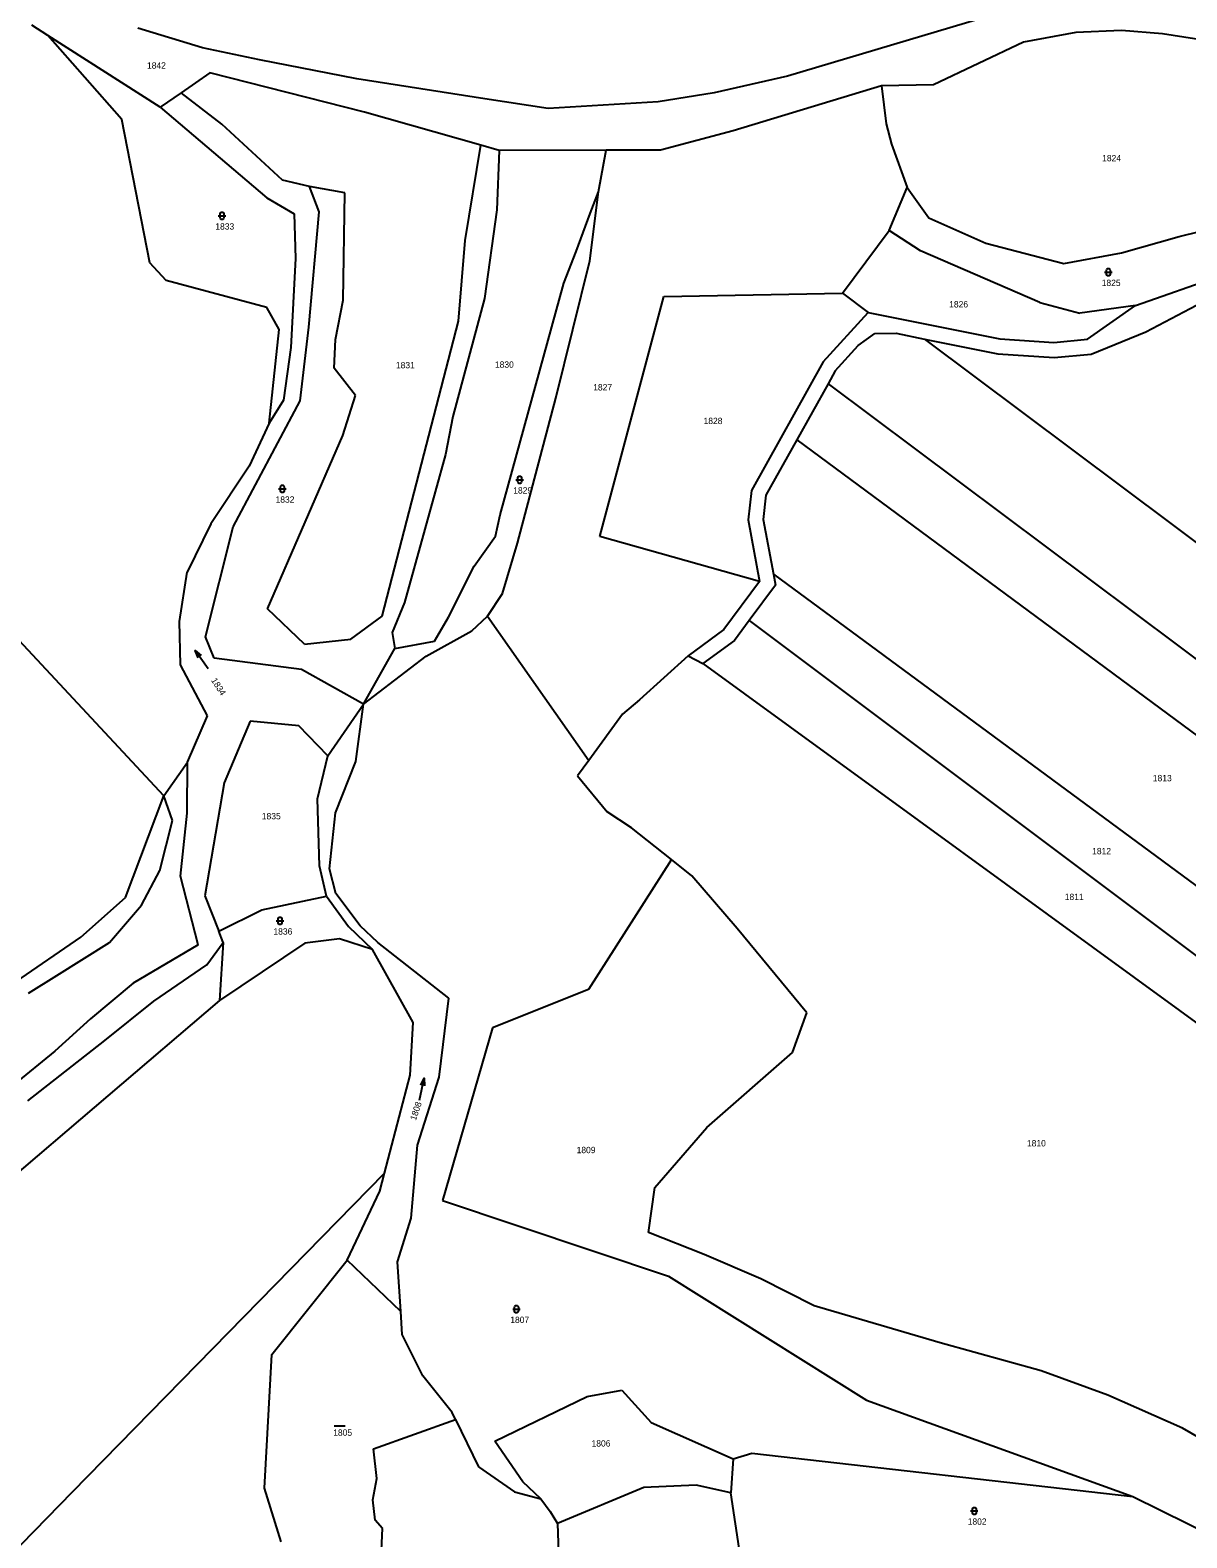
# Model space of a CAD drawing. Extents: x -802857 to -799647, y -1020285 to -1015884.
# Drawn here: x -802140.5 to -801830.8, y -1017652.7 to -1017248.9 of the extents above; entities that cross this region are included whole.
import ezdxf

# ---------------------------------------------------------------- set-up
doc = ezdxf.new("R2010")
doc.units = 0
for name, color, linetype in [('Default', 7, 'Continuous'), ('KN_HRANICE', 7, 'Continuous'), ('KN_KULTURY', 7, 'Continuous'), ('KN_PARCELY', 7, 'Continuous')]:
    doc.layers.add(name, color=color, linetype=linetype)

# ---------------------------------------------------------------- blocks, each defined once
blk = doc.blocks.new('316')
at = {"layer": 'Default'}
for points in [[(-1, 1), (0.27, 1), (1, 1)], [(-0.5, 1.5), (-0.4, 1.79), (-0.15, 1.97), (0.16, 1.97), (0.41, 1.79), (0.51, 1.5), (0.51, 0.5), (0.41, 0.21), (0.16, 0.03), (-0.15, 0.03), (-0.4, 0.21), (-0.5, 0.5), (-0.5, 1.5)]]:
    blk.add_lwpolyline(points, dxfattribs=at)
blk = doc.blocks.new('802')
at = {"layer": 'Default'}
blk.add_line((-3, 0), (3, 0), dxfattribs=at)
blk.add_lwpolyline([(1, 0.5), (3, 0), (1, -0.5)], dxfattribs=at)
blk = doc.blocks.new('804')
at = {"layer": 'Default'}
blk.add_line((-1.5, 0), (1.5, 0), dxfattribs=at)

msp = doc.modelspace()

# ---------------------------------------------------------------- linework, layer by layer
at = {"layer": 'KN_HRANICE'}
for p, q in [((-802135.82, -1017250.34), (-802140.07, -1017247.63)), ((-802094.38, -1017253.69), (-802111.69, -1017248.4)), ((-801885.86, -1017245.79), (-801937.77, -1017261.22)), ((-802115.97, -1017272.85), (-802135.82, -1017250.34)), ((-802105.66, -1017269.56), (-802135.82, -1017250.34)), ((-801874.58, -1017252.18), (-801898.61, -1017263.57)), ((-801860.52, -1017249.56), (-801874.58, -1017252.18)), ((-801848.33, -1017249.03), (-801860.52, -1017249.56)), ((-801837.36, -1017249.87), (-801848.33, -1017249.03)), ((-801825.91, -1017251.69), (-801837.36, -1017249.87)), ((-802079.15, -1017256.83), (-802094.38, -1017253.69)), ((-802092.36, -1017260.39), (-802100.06, -1017265.7)), ((-802050.96, -1017270.85), (-802092.36, -1017260.39)), ((-802053.05, -1017261.93), (-802079.15, -1017256.83)), ((-802018.77, -1017267.32), (-802053.05, -1017261.93)), ((-801937.77, -1017261.22), (-801957.35, -1017265.73)), ((-801912.59, -1017263.88), (-801952.27, -1017275.87)), ((-801898.61, -1017263.57), (-801912.59, -1017263.88)), ((-801912.59, -1017263.88), (-801911.34, -1017274.02)), ((-802100.06, -1017265.7), (-802105.66, -1017269.56)), ((-802089.22, -1017274.06), (-802100.06, -1017265.7)), ((-802001.86, -1017269.94), (-802018.77, -1017267.32)), ((-801972.34, -1017268.15), (-802001.86, -1017269.94)), ((-801957.35, -1017265.73), (-801972.34, -1017268.15)), ((-802105.66, -1017269.56), (-802077.17, -1017293.84)), ((-802019.81, -1017279.73), (-802050.96, -1017270.85)), ((-802108.43, -1017311.28), (-802115.97, -1017272.85)), ((-802072.93, -1017289.09), (-802089.22, -1017274.06)), ((-801952.27, -1017275.87), (-801971.78, -1017281.07)), ((-801911.34, -1017274.02), (-801909.91, -1017279.49)), ((-802024.05, -1017305.27), (-802019.81, -1017279.73)), ((-802014.98, -1017281.11), (-802019.81, -1017279.73)), ((-801909.91, -1017279.49), (-801905.73, -1017291.03)), ((-802014.98, -1017281.11), (-802015.53, -1017297.03)), ((-801986.28, -1017281.08), (-802014.98, -1017281.11)), ((-801988.37, -1017292.2), (-801986.28, -1017281.08)), ((-801971.78, -1017281.07), (-801986.28, -1017281.08)), ((-802065.76, -1017290.83), (-802072.93, -1017289.09)), ((-802063.17, -1017297.59), (-802065.76, -1017290.83)), ((-802056.25, -1017292.52), (-802065.76, -1017290.83)), ((-802056.66, -1017321.24), (-802056.25, -1017292.52)), ((-801990.7, -1017310.73), (-801988.37, -1017292.2)), ((-801990.6, -1017297.99), (-801988.37, -1017292.2)), ((-801910.52, -1017302.62), (-801905.73, -1017291.03)), ((-801905.73, -1017291.03), (-801899.92, -1017299.2)), ((-802077.17, -1017293.84), (-802069.8, -1017298.14)), ((-802015.53, -1017297.03), (-802018.85, -1017320.82)), ((-802069.8, -1017298.14), (-802069.48, -1017310.1)), ((-802065.91, -1017328.48), (-802063.17, -1017297.59)), ((-801994.28, -1017308.23), (-801990.6, -1017297.99)), ((-801899.92, -1017299.2), (-801884.62, -1017305.93)), ((-801832.86, -1017304.19), (-801816.89, -1017300.2)), ((-801922.99, -1017319.4), (-801910.52, -1017302.62)), ((-801902.09, -1017308), (-801910.52, -1017302.62)), ((-801848.32, -1017308.55), (-801832.86, -1017304.19)), ((-802025.84, -1017326.85), (-802024.05, -1017305.27)), ((-801997.65, -1017316.67), (-801994.28, -1017308.23)), ((-801870.21, -1017321.88), (-801902.09, -1017308)), ((-801884.62, -1017305.93), (-801863.71, -1017311.42)), ((-801863.71, -1017311.42), (-801848.32, -1017308.55)), ((-802104.1, -1017315.93), (-802108.43, -1017311.28)), ((-802069.48, -1017310.1), (-802070.75, -1017333.91)), ((-801999.74, -1017347.44), (-801990.7, -1017310.73)), ((-802104.72, -1017453.99), (-802234.28, -1017315.12)), ((-802077.12, -1017323.21), (-802104.1, -1017315.93)), ((-802014.71, -1017378.73), (-801997.65, -1017316.67)), ((-801844.56, -1017322.69), (-801821.66, -1017314.59)), ((-802058.72, -1017331.81), (-802056.66, -1017321.24)), ((-802018.85, -1017320.82), (-802027.34, -1017352.4)), ((-801987.95, -1017384.56), (-801970.88, -1017320.22)), ((-801970.88, -1017320.22), (-801922.99, -1017319.4)), ((-801922.99, -1017319.4), (-801916.15, -1017324.52)), ((-801841.82, -1017329.72), (-801824.8, -1017320.76)), ((-802073.83, -1017329.13), (-802077.12, -1017323.21)), ((-801928.21, -1017337.78), (-801916.15, -1017324.52)), ((-801916.15, -1017324.52), (-801880.89, -1017331.62)), ((-801870.21, -1017321.88), (-801859.44, -1017324.75)), ((-801844.56, -1017322.69), (-801859.44, -1017324.75)), ((-801857.38, -1017331.72), (-801844.56, -1017322.69)), ((-802076.48, -1017354.13), (-802073.83, -1017329.13)), ((-802068.2, -1017348.18), (-802065.91, -1017328.48)), ((-802046.3, -1017405.83), (-802025.84, -1017326.85)), ((-802059.12, -1017339.45), (-802058.72, -1017331.81)), ((-801924.94, -1017340.13), (-801918.78, -1017333.36)), ((-801918.78, -1017333.36), (-801914.38, -1017330.18)), ((-801914.38, -1017330.18), (-801908.67, -1017330.11)), ((-801908.67, -1017330.11), (-801901.1, -1017331.64)), ((-801901.1, -1017331.64), (-801881.43, -1017335.59)), ((-801901.1, -1017331.64), (-801752.52, -1017442.84)), ((-801880.89, -1017331.62), (-801866.4, -1017332.56)), ((-801866.4, -1017332.56), (-801857.38, -1017331.72)), ((-801856.42, -1017335.65), (-801841.82, -1017329.72)), ((-802070.75, -1017333.91), (-802072.65, -1017348.05)), ((-801881.43, -1017335.59), (-801866.34, -1017336.57)), ((-801866.34, -1017336.57), (-801856.42, -1017335.65)), ((-802053.38, -1017346.72), (-802059.12, -1017339.45)), ((-801928.21, -1017337.78), (-801947.39, -1017372.21)), ((-801924.94, -1017340.13), (-801926.87, -1017343.6)), ((-801926.87, -1017343.6), (-801935.26, -1017358.65)), ((-801926.87, -1017343.6), (-801768.75, -1017461.94)), ((-802086.2, -1017381.95), (-802068.2, -1017348.18)), ((-802072.65, -1017348.05), (-802076.48, -1017354.13)), ((-802056.78, -1017357.44), (-802053.38, -1017346.72)), ((-802010.06, -1017386.33), (-801999.74, -1017347.44)), ((-802027.34, -1017352.4), (-802029.33, -1017362.55)), ((-802076.48, -1017354.13), (-802081.89, -1017365.72)), ((-802076.93, -1017403.91), (-802056.78, -1017357.44)), ((-801935.26, -1017358.65), (-801943.51, -1017373.46)), ((-801935.26, -1017358.65), (-801779.08, -1017474.09)), ((-802029.33, -1017362.55), (-802034.83, -1017382.57)), ((-802081.89, -1017365.72), (-802092.18, -1017381.13)), ((-801947.39, -1017372.21), (-801948.3, -1017380.1)), ((-801943.51, -1017373.46), (-801944.26, -1017379.96)), ((-802092.18, -1017381.13), (-802098.46, -1017394.03)), ((-802015.89, -1017384.46), (-802014.71, -1017378.73)), ((-801948.3, -1017380.1), (-801945.23, -1017396.56)), ((-801944.26, -1017379.96), (-801941.53, -1017394.58)), ((-802093.54, -1017411.38), (-802086.2, -1017381.95)), ((-802034.83, -1017382.57), (-802040.31, -1017402.18)), ((-802021.65, -1017392.45), (-802015.89, -1017384.46)), ((-801945.23, -1017396.56), (-801987.95, -1017384.56)), ((-802014.08, -1017399.77), (-802010.06, -1017386.33)), ((-802028.5, -1017406.11), (-802021.65, -1017392.45)), ((-802100.54, -1017407.26), (-802098.46, -1017394.03)), ((-801945.23, -1017396.56), (-801954.81, -1017409.47)), ((-801940.98, -1017397.54), (-801947.99, -1017406.99)), ((-801941.53, -1017394.58), (-801940.98, -1017397.54)), ((-801941.53, -1017394.58), (-801799.52, -1017499.3)), ((-802018.05, -1017405.89), (-802014.08, -1017399.77)), ((-802067.06, -1017413.33), (-802076.93, -1017403.91)), ((-802054.67, -1017411.98), (-802046.3, -1017405.83)), ((-802040.31, -1017402.18), (-802043.62, -1017410.23)), ((-802022.25, -1017409.81), (-802018.05, -1017405.89)), ((-802018.05, -1017405.89), (-801990.91, -1017444.47)), ((-802100.23, -1017418.86), (-802100.54, -1017407.26)), ((-802034.52, -1017416.58), (-802022.25, -1017409.81)), ((-802032.22, -1017412.54), (-802028.5, -1017406.11)), ((-801954.81, -1017409.47), (-801964.29, -1017416.44)), ((-801947.99, -1017406.99), (-801951.96, -1017412.34)), ((-801947.99, -1017406.99), (-801809.18, -1017511.2)), ((-802091.22, -1017417.12), (-802093.54, -1017411.38)), ((-802067.06, -1017413.33), (-802054.67, -1017411.98)), ((-802043.62, -1017410.23), (-802042.85, -1017414.5)), ((-802042.85, -1017414.5), (-802032.22, -1017412.54)), ((-801951.96, -1017412.34), (-801960.43, -1017418.57)), ((-802067.89, -1017420.13), (-802091.22, -1017417.12)), ((-802051.27, -1017429.42), (-802042.85, -1017414.5)), ((-802051.27, -1017429.42), (-802034.52, -1017416.58)), ((-801964.29, -1017416.44), (-801977.33, -1017428.3)), ((-801964.29, -1017416.44), (-801960.43, -1017418.57)), ((-802093.06, -1017432.53), (-802100.23, -1017418.86)), ((-802051.27, -1017429.42), (-802067.89, -1017420.13)), ((-801960.43, -1017418.57), (-801819.24, -1017521.36)), ((-802060.85, -1017443.3), (-802051.27, -1017429.42)), ((-802053.3, -1017444.75), (-802051.27, -1017429.42)), ((-801977.33, -1017428.3), (-801981.94, -1017432.13)), ((-802098.34, -1017444.92), (-802093.06, -1017432.53)), ((-802081.64, -1017433.99), (-802088.57, -1017450.52)), ((-802068.53, -1017435.23), (-802081.64, -1017433.99)), ((-801981.94, -1017432.13), (-801990.91, -1017444.47)), ((-802060.85, -1017443.3), (-802068.53, -1017435.23)), ((-802104.72, -1017453.99), (-802098.34, -1017444.92)), ((-802098.44, -1017458.57), (-802098.34, -1017444.92)), ((-802063.57, -1017454.79), (-802060.85, -1017443.3)), ((-802058.8, -1017458.48), (-802053.3, -1017444.75)), ((-801990.91, -1017444.47), (-801993.92, -1017448.6)), ((-801993.92, -1017448.6), (-801986, -1017458.26)), ((-802115.01, -1017481.22), (-802104.72, -1017453.99)), ((-802102.44, -1017460.62), (-802104.72, -1017453.99)), ((-802088.57, -1017450.52), (-802093.7, -1017480.76)), ((-802063.08, -1017472.7), (-802063.57, -1017454.79)), ((-802060.32, -1017473.5), (-802058.8, -1017458.48)), ((-801979.48, -1017462.54), (-801986, -1017458.26)), ((-802105.82, -1017473.99), (-802102.44, -1017460.62)), ((-802100.3, -1017475.48), (-802098.44, -1017458.57)), ((-801968.81, -1017471.06), (-801979.48, -1017462.54)), ((-802110.74, -1017483.29), (-802105.82, -1017473.99)), ((-802061.2, -1017480.82), (-802063.08, -1017472.7)), ((-802058.68, -1017480.13), (-802060.32, -1017473.5)), ((-801968.81, -1017471.06), (-801991.01, -1017505.82)), ((-801963.34, -1017475.43), (-801968.81, -1017471.06)), ((-802095.56, -1017493.88), (-802100.3, -1017475.48)), ((-801951.18, -1017489.47), (-801963.34, -1017475.43)), ((-802126.91, -1017491.79), (-802115.01, -1017481.22)), ((-802093.7, -1017480.76), (-802089.98, -1017490.25)), ((-802078.47, -1017484.51), (-802061.2, -1017480.82)), ((-802061.2, -1017480.82), (-802055.25, -1017488.94)), ((-802052.12, -1017488.76), (-802058.68, -1017480.13)), ((-802119.31, -1017493.23), (-802110.74, -1017483.29)), ((-802089.98, -1017490.25), (-802078.47, -1017484.51)), ((-802088.79, -1017493.29), (-802089.98, -1017490.25)), ((-802055.25, -1017488.94), (-802048.87, -1017495.15)), ((-802047.43, -1017493.24), (-802052.12, -1017488.76)), ((-801932.6, -1017512.07), (-801951.18, -1017489.47)), ((-802144.39, -1017503.8), (-802126.91, -1017491.79)), ((-802133.41, -1017502.05), (-802119.31, -1017493.23)), ((-802095.56, -1017493.88), (-802112.95, -1017504.15)), ((-802093.25, -1017499.27), (-802088.79, -1017493.29)), ((-802088.79, -1017493.29), (-802089.8, -1017508.76)), ((-802066.93, -1017493.44), (-802089.8, -1017508.76)), ((-802057.71, -1017492.3), (-802066.93, -1017493.44)), ((-802048.87, -1017495.15), (-802057.71, -1017492.3)), ((-802028.39, -1017508.13), (-802047.43, -1017493.24)), ((-802037.98, -1017514.66), (-802048.87, -1017495.15)), ((-802140.95, -1017506.78), (-802133.41, -1017502.05)), ((-802107.41, -1017508.95), (-802093.25, -1017499.27)), ((-802112.95, -1017504.15), (-802124.38, -1017513.72)), ((-801991.01, -1017505.82), (-802016.71, -1017516.13)), ((-802089.8, -1017508.76), (-802158.4, -1017567.31)), ((-802120.51, -1017519.45), (-802107.41, -1017508.95)), ((-802031.03, -1017529.3), (-802028.39, -1017508.13)), ((-802124.38, -1017513.72), (-802133.87, -1017522.32)), ((-802038.74, -1017528.77), (-802037.98, -1017514.66)), ((-801936.43, -1017522.68), (-801932.6, -1017512.07)), ((-802016.71, -1017516.13), (-802030.12, -1017562.37)), ((-802133.87, -1017522.32), (-802145.05, -1017531.44)), ((-802141.11, -1017535.62), (-802120.51, -1017519.45)), ((-801959.3, -1017542.75), (-801936.43, -1017522.68)), ((-802045.6, -1017555.03), (-802038.74, -1017528.77)), ((-802036.81, -1017547.5), (-802031.03, -1017529.3)), ((-801973.25, -1017558.82), (-801959.3, -1017542.75)), ((-802038.48, -1017567.05), (-802036.81, -1017547.5)), ((-802129.14, -1017640.4), (-802045.6, -1017555.03)), ((-802046.85, -1017559.81), (-802045.6, -1017555.03)), ((-801974.92, -1017570.9), (-801973.25, -1017558.82)), ((-802055.66, -1017578.31), (-802046.85, -1017559.81)), ((-802030.12, -1017562.37), (-801969.63, -1017582.61)), ((-802042.13, -1017578.79), (-802038.48, -1017567.05)), ((-801960.08, -1017576.81), (-801974.92, -1017570.9)), ((-802075.83, -1017603.58), (-802055.66, -1017578.31)), ((-802041.24, -1017592.08), (-802055.66, -1017578.31)), ((-802041.24, -1017592.08), (-802042.13, -1017578.79)), ((-801944.86, -1017583.35), (-801960.08, -1017576.81)), ((-801969.63, -1017582.61), (-801916.56, -1017615.84)), ((-801930.62, -1017590.56), (-801944.86, -1017583.35)), ((-801896.85, -1017600.49), (-801930.62, -1017590.56)), ((-802040.91, -1017598.18), (-802041.24, -1017592.08)), ((-802035.33, -1017609.27), (-802040.91, -1017598.18)), ((-802077.76, -1017639.34), (-802075.83, -1017603.58)), ((-801869.8, -1017607.95), (-801896.85, -1017600.49)), ((-801852, -1017614.46), (-801869.8, -1017607.95)), ((-802027.48, -1017619.13), (-802035.33, -1017609.27)), ((-802016.11, -1017626.77), (-801991.36, -1017614.81)), ((-801991.36, -1017614.81), (-801982.05, -1017613.11)), ((-801982.05, -1017613.11), (-801974.22, -1017621.75)), ((-801916.56, -1017615.84), (-801845.29, -1017641.57)), ((-801832.01, -1017623.28), (-801852, -1017614.46)), ((-802026.6, -1017620.95), (-802027.48, -1017619.13)), ((-802048.6, -1017628.82), (-802026.6, -1017620.95)), ((-802026.6, -1017620.95), (-802020.45, -1017633.65)), ((-801974.22, -1017621.75), (-801952.31, -1017631.49)), ((-801804.69, -1017639.18), (-801832.01, -1017623.28)), ((-802008.63, -1017637.65), (-802016.11, -1017626.77)), ((-802047.68, -1017636.82), (-802048.6, -1017628.82)), ((-801952.31, -1017631.49), (-801952.94, -1017640.64)), ((-801952.31, -1017631.49), (-801947.31, -1017630)), ((-801947.31, -1017630), (-801845.29, -1017641.57)), ((-802020.45, -1017633.65), (-802010.81, -1017640.36)), ((-802073.29, -1017653.73), (-802077.76, -1017639.34)), ((-802048.77, -1017642.46), (-802047.68, -1017636.82)), ((-802003.75, -1017642.22), (-802008.63, -1017637.65)), ((-801976.22, -1017639.19), (-801999.28, -1017648.83)), ((-801962.21, -1017638.54), (-801976.22, -1017639.19)), ((-801952.94, -1017640.64), (-801962.21, -1017638.54)), ((-802214.72, -1017727.85), (-802129.14, -1017640.4)), ((-802048.15, -1017647.93), (-802048.77, -1017642.46)), ((-802010.81, -1017640.36), (-802003.75, -1017642.22)), ((-802003.75, -1017642.22), (-802001.28, -1017645.63)), ((-801950.38, -1017657.2), (-801952.94, -1017640.64)), ((-801845.29, -1017641.57), (-801823.05, -1017652.62)), ((-802046.13, -1017650.15), (-802048.15, -1017647.93)), ((-802001.28, -1017645.63), (-801999.28, -1017648.83)), ((-802046.96, -1017667.05), (-802046.13, -1017650.15)), ((-801999.28, -1017648.83), (-801998.77, -1017663.53))]:
    msp.add_line(p, q, dxfattribs=at)

# ---------------------------------------------------------------- block references
at = {"layer": 'KN_KULTURY'}
for name, p in [('316', (-802089.13, -1017299.63)), ('316', (-801851.84, -1017314.75)), ('316', (-802009.45, -1017370.32)), ('316', (-802073.01, -1017372.77)), ('316', (-802073.63, -1017488.44)), ('316', (-802010.31, -1017592.45)), ('804', (-802057.65, -1017622.65)), ('316', (-801887.74, -1017646.48))]:
    msp.add_blockref(name, p, dxfattribs=at)
for p, rotation in [((-802094.57, -1017417.5), 125.42046100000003), ((-802035.62, -1017532.53), 78.20873900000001)]:
    msp.add_blockref('802', p, dxfattribs=dict(at, rotation=rotation))

# ---------------------------------------------------------------- texts
at = {"layer": 'KN_PARCELY'}
for s, p in [('1842', (-802109.23, -1017259.23)), ('1824', (-801853.49, -1017284.04)), ('1833', (-802090.94, -1017302.33)), ('1825', (-801853.61, -1017317.45)), ('1826', (-801894.45, -1017323.19)), ('1831', (-802042.58, -1017339.48)), ('1830', (-802016.07, -1017339.33)), ('1827', (-801989.76, -1017345.42)), ('1828', (-801960.21, -1017354.42)), ('1832', (-802074.81, -1017375.47)), ('1829', (-802011.17, -1017373.02)), ('1813', (-801839.92, -1017450.07)), ('1835', (-802078.48, -1017460.27)), ('1812', (-801856.17, -1017469.62)), ('1811', (-801863.5, -1017481.88)), ('1836', (-802075.37, -1017491.14)), ('1810', (-801873.63, -1017547.86)), ('1809', (-801994.2, -1017549.67)), ('1807', (-802011.96, -1017595.15)), ('1805', (-802059.37, -1017625.35)), ('1806', (-801990.2, -1017628.23)), ('1802', (-801889.49, -1017649.18))]:
    msp.add_text(s, height=1.7, dxfattribs=at).set_placement(p)
for s, rotation, p in [('1834', 302.579, (-802092.12, -1017423.05)), ('1808', 71.562, (-802037.24, -1017541.04))]:
    msp.add_text(s, height=1.7, rotation=rotation, dxfattribs=at).set_placement(p)

doc.saveas('drawing.dxf')
